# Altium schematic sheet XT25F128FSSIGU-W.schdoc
size 127 x 101 mm
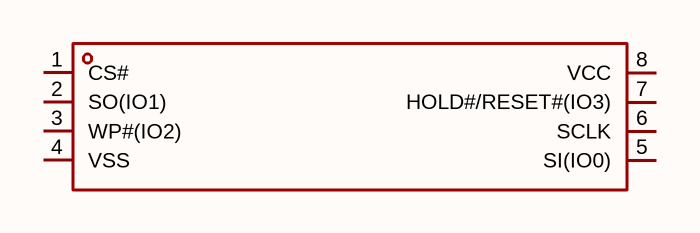
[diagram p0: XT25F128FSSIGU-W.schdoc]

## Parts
U?  xt25f128fssigu-w  [SOIC-8_L5.3-W5.3-P1.27-LS7.9-BL]  (value not drawn)

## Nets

Not connected (* = marked no-connect by the designer): U? 1(CS#) 2(SO(IO1)) 3(WP#(IO2)) 4(VSS) 5(SI(IO0)) 6(SCLK) 7(HOLD#/RESET#(IO3)) 8(VCC)

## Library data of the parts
U? = xt25f128fssigu-w: 接口类型:SPI;存储容量:128Mbit;时钟频率(fc):133MHz;; Manufacturer: XTX(芯天下); AddInBom: yes; ModelId: 78e311bc6cdb4f2a8ea91f8efea56c7d; ModelTransform: 311.023,207.8736,0,90,0,0,0,0,0; Interface: SPI; Clock Frequency: 133MHz; Voltage - Supply: 2.7V~3.6V; Standby Supply Current: 0.5uA; Program / Erase Cycles: 100000次; Page Programming Time (Tpp): 400us; Block Erase Time(tBE): 250ms@(64KB); Data Retention - TDR (Year): 20年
